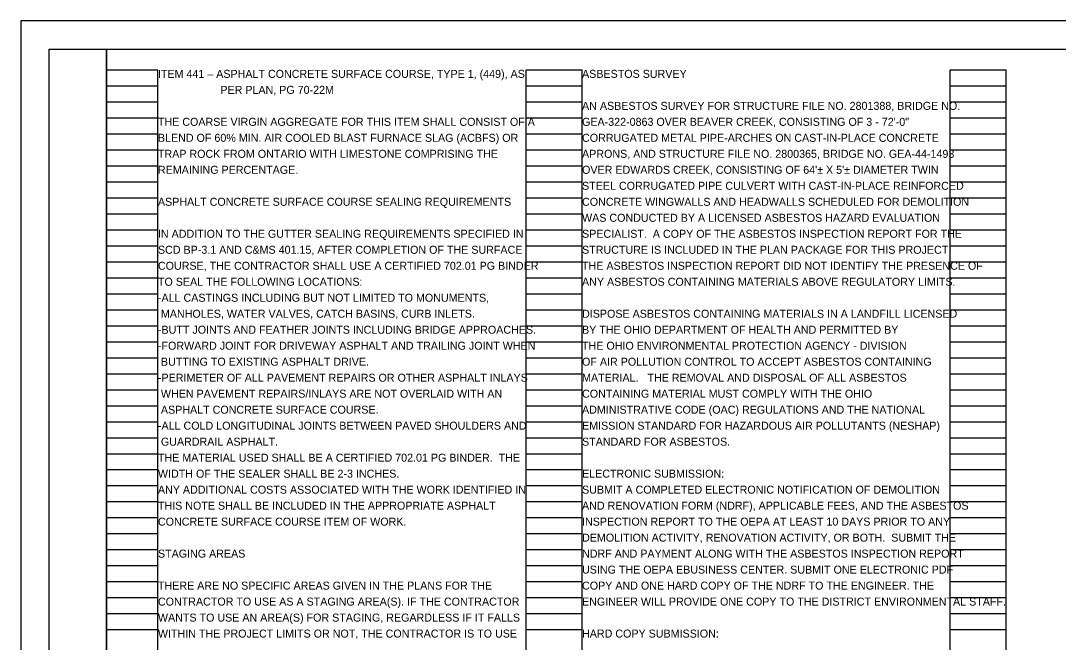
# Model space of a CAD drawing. Extents: x 0 to 36.3, y 0 to 22.
# Drawn here: x 0 to 18.15, y 11.12 to 22 of the extents above; entities that cross this region are included whole.
import ezdxf

# ---------------------------------------------------------------- set-up
doc = ezdxf.new("R2010")
doc.units = 0
for name, color, linetype in [('SH_Border', 7, 'Continuous'), ('SH_Cut_Line', 7, 'Continuous'), ('SH_Data', 7, 'Continuous'), ('SH_Text', 7, 'Continuous')]:
    doc.layers.add(name, color=color, linetype=linetype)

msp = doc.modelspace()

# ---------------------------------------------------------------- linework, layer by layer
at = {"layer": 'SH_Border'}
for points in [[(0.5, 21.5), (1.5, 21.5), (1.5, 0.5), (0.5, 0.5)], [(1.5, 21.5), (33.5, 21.5), (33.5, 0.5), (1.5, 0.5)]]:
    msp.add_lwpolyline(points, close=True, dxfattribs=at)
at = {"layer": 'SH_Cut_Line'}
msp.add_lwpolyline([(0, 0), (34, 0), (34, 22), (0, 22)], close=True, dxfattribs=at)
at = {"layer": 'SH_Data'}
for p, q in [((1.5, 0.98), (1.5, 21.14)), ((1.5, 21.14), (2.4, 21.14)), ((2.4, 0.98), (2.4, 21.14)), ((8.84, 0.98), (8.84, 21.14)), ((8.84, 21.14), (9.82, 21.14)), ((9.82, 0.98), (9.82, 21.14)), ((16.26, 0.98), (16.26, 21.14)), ((16.26, 21.14), (17.24, 21.14)), ((17.24, 0.98), (17.24, 21.14)), ((1.5, 20.86), (2.4, 20.86)), ((8.84, 20.86), (9.82, 20.86)), ((16.26, 20.86), (17.24, 20.86)), ((1.5, 20.58), (2.4, 20.58)), ((8.84, 20.58), (9.82, 20.58)), ((16.26, 20.58), (17.24, 20.58)), ((1.5, 20.3), (2.4, 20.3)), ((8.84, 20.3), (9.82, 20.3)), ((16.26, 20.3), (17.24, 20.3)), ((1.5, 20.02), (2.4, 20.02)), ((8.84, 20.02), (9.82, 20.02)), ((16.26, 20.02), (17.24, 20.02)), ((1.5, 19.74), (2.4, 19.74)), ((8.84, 19.74), (9.82, 19.74)), ((16.26, 19.74), (17.24, 19.74)), ((1.5, 19.46), (2.4, 19.46)), ((8.84, 19.46), (9.82, 19.46)), ((16.26, 19.46), (17.24, 19.46)), ((1.5, 19.18), (2.4, 19.18)), ((8.84, 19.18), (9.82, 19.18)), ((16.26, 19.18), (17.24, 19.18)), ((1.5, 18.9), (2.4, 18.9)), ((8.84, 18.9), (9.82, 18.9)), ((16.26, 18.9), (17.24, 18.9)), ((1.5, 18.62), (2.4, 18.62)), ((8.84, 18.62), (9.82, 18.62)), ((16.26, 18.62), (17.24, 18.62)), ((1.5, 18.34), (2.4, 18.34)), ((8.84, 18.34), (9.82, 18.34)), ((16.26, 18.34), (17.24, 18.34)), ((1.5, 18.06), (2.4, 18.06)), ((8.84, 18.06), (9.82, 18.06)), ((16.26, 18.06), (17.24, 18.06)), ((1.5, 17.78), (2.4, 17.78)), ((8.84, 17.78), (9.82, 17.78)), ((16.26, 17.78), (17.24, 17.78)), ((1.5, 17.5), (2.4, 17.5)), ((8.84, 17.5), (9.82, 17.5)), ((16.26, 17.5), (17.24, 17.5)), ((1.5, 17.22), (2.4, 17.22)), ((8.84, 17.22), (9.82, 17.22)), ((16.26, 17.22), (17.24, 17.22)), ((1.5, 16.94), (2.4, 16.94)), ((8.84, 16.94), (9.82, 16.94)), ((16.26, 16.94), (17.24, 16.94)), ((1.5, 16.66), (2.4, 16.66)), ((8.84, 16.66), (9.82, 16.66)), ((16.26, 16.66), (17.24, 16.66)), ((1.5, 16.38), (2.4, 16.38)), ((8.84, 16.38), (9.82, 16.38)), ((16.26, 16.38), (17.24, 16.38)), ((1.5, 16.1), (2.4, 16.1)), ((8.84, 16.1), (9.82, 16.1)), ((16.26, 16.1), (17.24, 16.1)), ((1.5, 15.82), (2.4, 15.82)), ((8.84, 15.82), (9.82, 15.82)), ((16.26, 15.82), (17.24, 15.82)), ((1.5, 15.54), (2.4, 15.54)), ((8.84, 15.54), (9.82, 15.54)), ((16.26, 15.54), (17.24, 15.54)), ((1.5, 15.26), (2.4, 15.26)), ((8.84, 15.26), (9.82, 15.26)), ((16.26, 15.26), (17.24, 15.26)), ((1.5, 14.98), (2.4, 14.98)), ((8.84, 14.98), (9.82, 14.98)), ((16.26, 14.98), (17.24, 14.98)), ((1.5, 14.7), (2.4, 14.7)), ((8.84, 14.7), (9.82, 14.7)), ((16.26, 14.7), (17.24, 14.7)), ((1.5, 14.42), (2.4, 14.42)), ((8.84, 14.42), (9.82, 14.42)), ((16.26, 14.42), (17.24, 14.42)), ((1.5, 14.14), (2.4, 14.14)), ((8.84, 14.14), (9.82, 14.14)), ((16.26, 14.14), (17.24, 14.14)), ((1.5, 13.86), (2.4, 13.86)), ((8.84, 13.86), (9.82, 13.86)), ((16.26, 13.86), (17.24, 13.86)), ((1.5, 13.58), (2.4, 13.58)), ((8.84, 13.58), (9.82, 13.58)), ((16.26, 13.58), (17.24, 13.58)), ((1.5, 13.3), (2.4, 13.3)), ((8.84, 13.3), (9.82, 13.3)), ((16.26, 13.3), (17.24, 13.3)), ((1.5, 13.02), (2.4, 13.02)), ((8.84, 13.02), (9.82, 13.02)), ((16.26, 13.02), (17.24, 13.02)), ((1.5, 12.74), (2.4, 12.74)), ((8.84, 12.74), (9.82, 12.74)), ((16.26, 12.74), (17.24, 12.74)), ((1.5, 12.46), (2.4, 12.46)), ((8.84, 12.46), (9.82, 12.46)), ((16.26, 12.46), (17.24, 12.46)), ((1.5, 12.18), (2.4, 12.18)), ((8.84, 12.18), (9.82, 12.18)), ((16.26, 12.18), (17.24, 12.18)), ((1.5, 11.9), (2.4, 11.9)), ((8.84, 11.9), (9.82, 11.9)), ((16.26, 11.9), (17.24, 11.9)), ((1.5, 11.62), (2.4, 11.62)), ((8.84, 11.62), (9.82, 11.62)), ((16.26, 11.62), (17.24, 11.62)), ((1.5, 11.34), (2.4, 11.34)), ((8.84, 11.34), (9.82, 11.34)), ((16.26, 11.34), (17.24, 11.34))]:
    msp.add_line(p, q, dxfattribs=at)

# ---------------------------------------------------------------- texts
at = {"layer": 'SH_Text'}
for s, p in [('ITEM 441 – ASPHALT CONCRETE SURFACE COURSE, TYPE 1, (449), AS', (2.4, 21)), ('ASBESTOS SURVEY', (9.82, 21)), ('                     PER PLAN, PG 70-22M', (2.4, 20.72)), ('AN ASBESTOS SURVEY FOR STRUCTURE FILE NO. 2801388, BRIDGE NO.', (9.82, 20.44)), ('THE COARSE VIRGIN AGGREGATE FOR THIS ITEM SHALL CONSIST OF A', (2.4, 20.16)), ('GEA-322-0863 OVER BEAVER CREEK, CONSISTING OF 3 - 72\'-0"', (9.82, 20.16)), ('BLEND OF 60% MIN. AIR COOLED BLAST FURNACE SLAG (ACBFS) OR', (2.4, 19.88)), ('CORRUGATED METAL PIPE-ARCHES ON CAST-IN-PLACE CONCRETE', (9.82, 19.88)), ('TRAP ROCK FROM ONTARIO WITH LIMESTONE COMPRISING THE', (2.4, 19.6)), ('APRONS, AND STRUCTURE FILE NO. 2800365, BRIDGE NO. GEA-44-1493', (9.82, 19.6)), ('REMAINING PERCENTAGE.', (2.4, 19.32)), ("OVER EDWARDS CREEK, CONSISTING OF 64'± X 5'± DIAMETER TWIN", (9.82, 19.32)), ('STEEL CORRUGATED PIPE CULVERT WITH CAST-IN-PLACE REINFORCED', (9.82, 19.04)), ('ASPHALT CONCRETE SURFACE COURSE SEALING REQUIREMENTS', (2.4, 18.76)), ('CONCRETE WINGWALLS AND HEADWALLS SCHEDULED FOR DEMOLITION', (9.82, 18.76)), ('WAS CONDUCTED BY A LICENSED ASBESTOS HAZARD EVALUATION ', (9.82, 18.48)), ('IN ADDITION TO THE GUTTER SEALING REQUIREMENTS SPECIFIED IN', (2.4, 18.2)), ('SPECIALIST.  A COPY OF THE ASBESTOS INSPECTION REPORT FOR THE ', (9.82, 18.2)), ('SCD BP-3.1 AND C&MS 401.15, AFTER COMPLETION OF THE SURFACE', (2.4, 17.92)), ('STRUCTURE IS INCLUDED IN THE PLAN PACKAGE FOR THIS PROJECT.  ', (9.82, 17.92)), ('COURSE, THE CONTRACTOR SHALL USE A CERTIFIED 702.01 PG BINDER', (2.4, 17.64)), ('THE ASBESTOS INSPECTION REPORT DID NOT IDENTIFY THE PRESENCE OF ', (9.82, 17.64)), ('TO SEAL THE FOLLOWING LOCATIONS:', (2.4, 17.36)), ('ANY ASBESTOS CONTAINING MATERIALS ABOVE REGULATORY LIMITS.  ', (9.82, 17.36)), ('-ALL CASTINGS INCLUDING BUT NOT LIMITED TO MONUMENTS,', (2.4, 17.08)), (' MANHOLES, WATER VALVES, CATCH BASINS, CURB INLETS.', (2.4, 16.8)), ('DISPOSE ASBESTOS CONTAINING MATERIALS IN A LANDFILL LICENSED', (9.82, 16.8)), ('-BUTT JOINTS AND FEATHER JOINTS INCLUDING BRIDGE APPROACHES.', (2.4, 16.52)), ('BY THE OHIO DEPARTMENT OF HEALTH AND PERMITTED BY ', (9.82, 16.52)), ('-FORWARD JOINT FOR DRIVEWAY ASPHALT AND TRAILING JOINT WHEN', (2.4, 16.24)), ('THE OHIO ENVIRONMENTAL PROTECTION AGENCY - DIVISION ', (9.82, 16.24)), (' BUTTING TO EXISTING ASPHALT DRIVE.', (2.4, 15.96)), ('OF AIR POLLUTION CONTROL TO ACCEPT ASBESTOS CONTAINING ', (9.82, 15.96)), ('-PERIMETER OF ALL PAVEMENT REPAIRS OR OTHER ASPHALT INLAYS', (2.4, 15.68)), ('MATERIAL.   THE REMOVAL AND DISPOSAL OF ALL ASBESTOS ', (9.82, 15.68)), (' WHEN PAVEMENT REPAIRS/INLAYS ARE NOT OVERLAID WITH AN', (2.4, 15.4)), ('CONTAINING MATERIAL MUST COMPLY WITH THE OHIO ', (9.82, 15.4)), (' ASPHALT CONCRETE SURFACE COURSE.', (2.4, 15.12)), ('ADMINISTRATIVE CODE (OAC) REGULATIONS AND THE NATIONAL', (9.82, 15.12)), ('-ALL COLD LONGITUDINAL JOINTS BETWEEN PAVED SHOULDERS AND', (2.4, 14.84)), ('EMISSION STANDARD FOR HAZARDOUS AIR POLLUTANTS (NESHAP) ', (9.82, 14.84)), (' GUARDRAIL ASPHALT.', (2.4, 14.56)), ('STANDARD FOR ASBESTOS.', (9.82, 14.56)), ('THE MATERIAL USED SHALL BE A CERTIFIED 702.01 PG BINDER.  THE', (2.4, 14.28)), ('WIDTH OF THE SEALER SHALL BE 2-3 INCHES.  ', (2.4, 14)), ('ELECTRONIC SUBMISSION:  ', (9.82, 14)), ('ANY ADDITIONAL COSTS ASSOCIATED WITH THE WORK IDENTIFIED IN', (2.4, 13.72)), ('SUBMIT A COMPLETED ELECTRONIC NOTIFICATION OF DEMOLITION', (9.82, 13.72)), ('THIS NOTE SHALL BE INCLUDED IN THE APPROPRIATE ASPHALT', (2.4, 13.44)), ('AND RENOVATION FORM (NDRF), APPLICABLE FEES, AND THE ASBESTOS ', (9.82, 13.44)), ('CONCRETE SURFACE COURSE ITEM OF WORK.  ', (2.4, 13.16)), ('INSPECTION REPORT TO THE OEPA AT LEAST 10 DAYS PRIOR TO ANY ', (9.82, 13.16)), ('DEMOLITION ACTIVITY, RENOVATION ACTIVITY, OR BOTH.  SUBMIT THE ', (9.82, 12.88)), ('STAGING AREAS', (2.4, 12.6)), ('NDRF AND PAYMENT ALONG WITH THE ASBESTOS INSPECTION REPORT ', (9.82, 12.6)), ('USING THE OEPA EBUSINESS CENTER. SUBMIT ONE ELECTRONIC PDF ', (9.82, 12.32)), ('THERE ARE NO SPECIFIC AREAS GIVEN IN THE PLANS FOR THE', (2.4, 12.04)), ('COPY AND ONE HARD COPY OF THE NDRF TO THE ENGINEER. THE ', (9.82, 12.04)), ('CONTRACTOR TO USE AS A STAGING AREA(S). IF THE CONTRACTOR', (2.4, 11.76)), ('ENGINEER WILL PROVIDE ONE COPY TO THE DISTRICT ENVIRONMENTAL STAFF.', (9.82, 11.76)), ('WANTS TO USE AN AREA(S) FOR STAGING, REGARDLESS IF IT FALLS', (2.4, 11.48)), ('WITHIN THE PROJECT LIMITS OR NOT, THE CONTRACTOR IS TO USE', (2.4, 11.2)), ('HARD COPY SUBMISSION:', (9.82, 11.2))]:
    msp.add_text(s, height=0.14, dxfattribs=at).set_placement(p)

doc.saveas('drawing.dxf')
